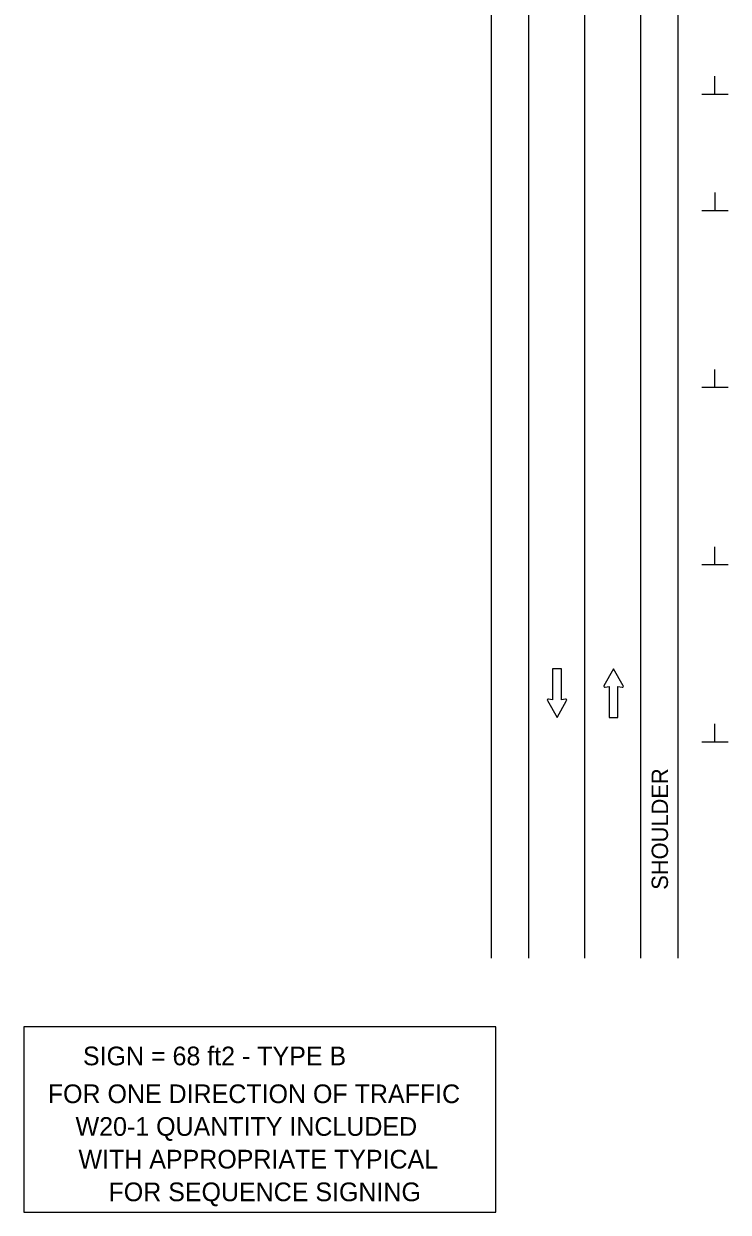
# Model space of a CAD drawing. Extents: x 19023 to 20747, y 5121 to 6119.
# Drawn here: x 19023 to 19325, y 5152 to 5661 of the extents above; entities that cross this region are included whole.
import ezdxf

# ---------------------------------------------------------------- set-up
doc = ezdxf.new("R2010")
doc.units = 0
for name, color, linetype in [('MT_SCRATCH_LEVEL_E', 7, 'Continuous'), ('PAVT_EDGE_EX', 7, 'Continuous'), ('TYPICAL_TEXT_DIMEN_PR', 7, 'Continuous')]:
    doc.layers.add(name, color=color, linetype=linetype)

msp = doc.modelspace()

# ---------------------------------------------------------------- linework, layer by layer
at = {"layer": 'MT_SCRATCH_LEVEL_E'}
for p, q in [((19253.189, 5384.987), (19249.447, 5384.987)), ((19249.447, 5384.987), (19249.447, 5371.729)), ((19253.189, 5384.987), (19249.447, 5384.987)), ((19249.447, 5384.987), (19249.447, 5371.729)), ((19253.189, 5371.729), (19253.189, 5384.987)), ((19253.189, 5371.729), (19253.189, 5384.987)), ((19275.531, 5384.986), (19271.42, 5377.745)), ((19275.531, 5384.986), (19271.42, 5377.745)), ((19279.678, 5377.745), (19275.531, 5384.986)), ((19279.678, 5377.745), (19275.531, 5384.986)), ((19271.902, 5377.061), (19273.679, 5377.377)), ((19271.902, 5377.061), (19273.679, 5377.377)), ((19273.679, 5377.377), (19273.679, 5364.119)), ((19273.679, 5377.377), (19273.679, 5364.119)), ((19277.421, 5364.119), (19277.421, 5377.377)), ((19277.421, 5377.377), (19279.199, 5377.061)), ((19277.421, 5364.119), (19277.421, 5377.377)), ((19277.421, 5377.377), (19279.199, 5377.061)), ((19247.19, 5371.361), (19251.337, 5364.12)), ((19247.19, 5371.361), (19251.337, 5364.12)), ((19249.447, 5371.729), (19247.669, 5372.045)), ((19249.447, 5371.729), (19247.669, 5372.045)), ((19251.337, 5364.12), (19255.448, 5371.361)), ((19251.337, 5364.12), (19255.448, 5371.361)), ((19254.966, 5372.045), (19253.189, 5371.729)), ((19254.966, 5372.045), (19253.189, 5371.729)), ((19273.679, 5364.119), (19277.421, 5364.119)), ((19273.679, 5364.119), (19277.421, 5364.119))]:
    msp.add_line(p, q, dxfattribs=at)
for centre, start, end in [((19271.828, 5377.521), 150.42484, 279.96381), ((19271.828, 5377.521), 150.42484, 279.96381), ((19279.268, 5377.522), 260.03619, 29.77312), ((19279.268, 5377.522), 260.03619, 29.77312), ((19247.6, 5371.584), 80.03619, 209.77312), ((19247.6, 5371.584), 80.03619, 209.77312), ((19255.04, 5371.585), 330.42484, 99.96381), ((19255.04, 5371.585), 330.42484, 99.96381)]:
    msp.add_arc(centre, 0.463, start, end, dxfattribs=at)
at = {"layer": 'PAVT_EDGE_EX'}
for p, q in [((19223.086, 6104.026), (19223.086, 5261.047)), ((19239.086, 6104.026), (19239.086, 5261.047)), ((19287.086, 6104.026), (19287.086, 5261.047)), ((19303.086, 6104.026), (19303.086, 5261.047)), ((19239.086, 6014.455), (19239.086, 5261.047)), ((19263.086, 6014.455), (19263.086, 5261.047))]:
    msp.add_line(p, q, dxfattribs=at)
for points in [[(19263.086, 5614.455), (19263.086, 5589.455)], [(19263.086, 5514.455), (19263.086, 5489.455)], [(19263.086, 5414.455), (19263.086, 5389.455)], [(19263.086, 5314.455), (19263.086, 5289.455)]]:
    msp.add_lwpolyline(points, dxfattribs=at)
at = {"layer": 'TYPICAL_TEXT_DIMEN_PR'}
for p, q in [((19318.925, 5630.918), (19318.925, 5638.703)), ((19318.925, 5630.918), (19313.3, 5630.918)), ((19324.55, 5630.918), (19318.925, 5630.918)), ((19318.989, 5581.084), (19318.989, 5588.869)), ((19318.989, 5581.084), (19313.364, 5581.084)), ((19324.614, 5581.084), (19318.989, 5581.084)), ((19318.904, 5505.41), (19318.904, 5513.195)), ((19318.93, 5505.41), (19318.93, 5513.195)), ((19318.904, 5505.41), (19313.279, 5505.41)), ((19318.93, 5505.41), (19313.305, 5505.41)), ((19324.529, 5505.41), (19318.904, 5505.41)), ((19324.555, 5505.41), (19318.93, 5505.41)), ((19318.93, 5429.493), (19318.93, 5437.278)), ((19318.93, 5429.493), (19313.305, 5429.493)), ((19324.555, 5429.493), (19318.93, 5429.493)), ((19318.93, 5353.576), (19318.93, 5361.361)), ((19318.93, 5353.576), (19313.305, 5353.576)), ((19324.555, 5353.576), (19318.93, 5353.576))]:
    msp.add_line(p, q, dxfattribs=at)
msp.add_lwpolyline([(19023.032, 5152.303), (19225.062, 5152.303), (19225.062, 5231.677), (19023.032, 5231.677)], close=True, dxfattribs=at)

# ---------------------------------------------------------------- texts
msp.add_text('SHOULDER', height=7, rotation=90, dxfattribs=at).set_placement((19298.829, 5290.377))
for s, p in [('SIGN = 68 ft2 - TYPE B', (19048.373, 5215.218)), ('FOR ONE DIRECTION OF TRAFFIC', (19033.32, 5199.024)), ('W20-1 QUANTITY INCLUDED ', (19045.212, 5185.024)), ('WITH APPROPRIATE TYPICAL', (19046.461, 5171.024)), ('FOR SEQUENCE SIGNING', (19059.313, 5157.024))]:
    msp.add_text(s, height=8, dxfattribs=at).set_placement(p)

doc.saveas('drawing.dxf')
